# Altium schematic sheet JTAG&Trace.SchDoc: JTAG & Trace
size A4; DocumentNumber: MB1165; Revision: C.1; SheetNumber: 17; SheetTotal: 17; Project: STM32469I-EVAL
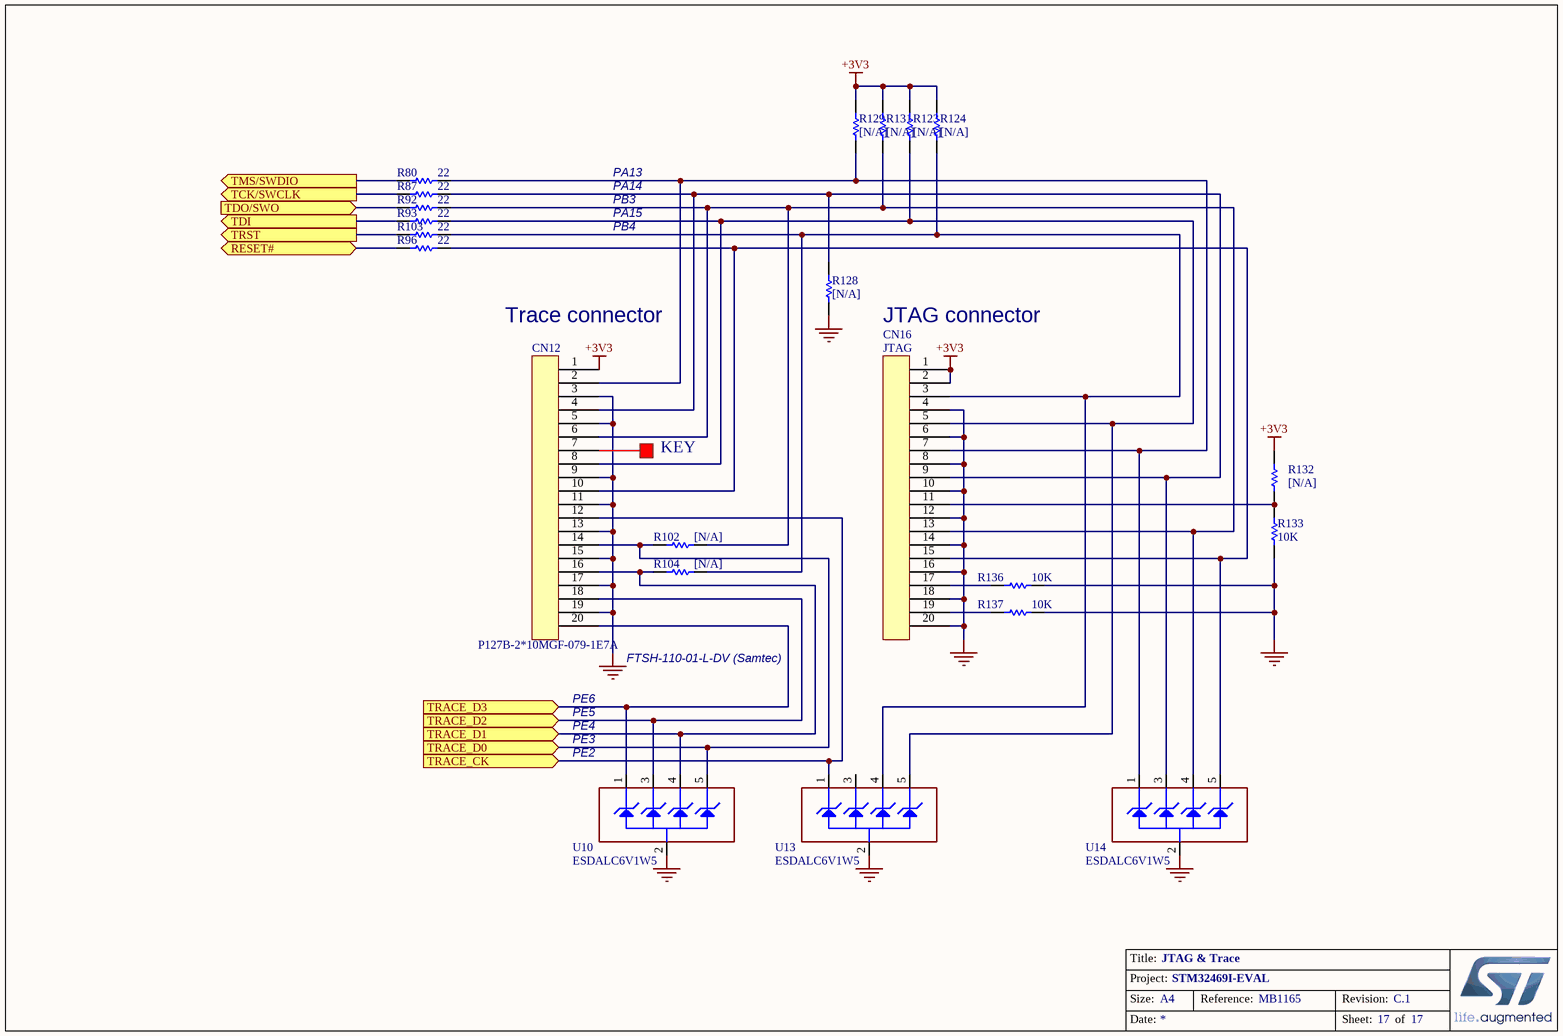
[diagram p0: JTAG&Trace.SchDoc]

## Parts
CN12  P127B-2*10MGF-079-1E7A  [FTSH-110-01-L-DV]
CN16  JTAG  [IDC20S]
R80  22  [0603R]
R87  22  [0603R]
R92  22  [0603R]
R93  22  [0603R]
R96  22  [0603R]
R102  [N/A]  [0603R]
R103  22  [0603R]
R104  [N/A]  [0603R]
R123  [N/A]  [0603R]
R124  [N/A]  [0603R]
R128  [N/A]  [0603R]
R129  [N/A]  [0603R]
R131  [N/A]  [0603R]
R132  [N/A]  [0603R]
R133  10K  [0603R]
R136  10K  [0603R]
R137  10K  [0603R]
U10  ESDALC6V1W5  [SOT-353]
U13  ESDALC6V1W5  [SOT-353]
U14  ESDALC6V1W5  [SOT-353]

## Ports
RESET# (bidir), TCK/SWCLK (out), TDI (out), TDO/SWO (in), TMS/SWDIO (out), TRACE_CK (in), TRACE_D0 (in), TRACE_D1 (in), TRACE_D2 (in), TRACE_D3 (in), TRST (out)

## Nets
+3V3: CN12.1 CN16.1 CN16.2 R123.2 R124.2 R129.2 R131.2 R132.2
GND: CN12.3 CN12.5 CN12.9 CN12.11 CN12.13 CN12.15 CN12.17 CN12.19 CN16.4 CN16.6 CN16.8 CN16.10 CN16.12 CN16.14 CN16.16 CN16.18 CN16.20 R128.1 R133.1 R136.1 R137.1 U10.2(GND) U13.2(GND) U14.2(GND)
RESET#: R96.2 ; port RESET#
TCK/SWCLK: R87.2 ; port TCK/SWCLK
TDI: R93.2 ; port TDI
TDO/SWO: R92.2 ; port TDO/SWO
TMS/SWDIO: R80.2 ; port TMS/SWDIO
TRACE_CK: CN12.12 U13.1(IO1) ; port TRACE_CK
TRACE_D0: CN12.14 R102.1 U10.5(IO4) ; port TRACE_D0
TRACE_D1: CN12.16 R104.1 U10.4(IO3) ; port TRACE_D1
TRACE_D2: CN12.18 U10.3(IO2) ; port TRACE_D2
TRACE_D3: CN12.20 U10.1(IO1) ; port TRACE_D3
TRST: R103.2 ; port TRST
NetCN12_2: CN12.2 CN16.7 R80.1 R129.1 U14.1(IO1)
NetCN12_4: CN12.4 CN16.9 R87.1 R128.2 U14.3(IO2)
NetCN12_6: CN12.6 CN16.13 R92.1 R102.2 R131.1 U14.4(IO3)
NetCN12_8: CN12.8 CN16.5 R93.1 R123.1 U13.5(IO4)
NetCN12_10: CN12.10 CN16.15 R96.1 U14.5(IO4)
NetCN16_3: CN16.3 R103.1 R104.2 R124.1 U13.4(IO3)
NetCN16_11: CN16.11 R132.1 R133.2
NetCN16_17: CN16.17 R136.2
NetCN16_19: CN16.19 R137.2

Not connected (* = marked no-connect by the designer): CN12 7; U13 3(IO2)

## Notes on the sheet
- PA13
- PA14
- PB3
- PA15
- PB4
- (near CN12) Trace connector
- JTAG connector
- KEY
- PE6
- PE5
- (near CN12) FTSH-110-01-L-DV (Samtec)
- PE4
- PE3
- (near U10) PE2

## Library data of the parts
CN12 CN16 = 20PIN1
R80 R87 R92 R93 R96 R102-R104 R123 R124 R128 R129 R131-R133 R136 R137 = Res1: Resistor; Value: 1K
U10 U13 U14 = ESDALC6V1W5: Dual Transil array for ESD protection; Manuf_1: STM; Manuf_Part_1: ESDA5V3L; Ref St: 9179034; Provided: ST; ECCN_US/EU: EAR99/NEC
